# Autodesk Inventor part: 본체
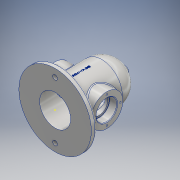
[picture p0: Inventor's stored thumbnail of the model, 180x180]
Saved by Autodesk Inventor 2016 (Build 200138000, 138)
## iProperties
Created: 2019-11
Part Number: 본체
Material: 알루미늄 6061
Document SubType Name: Modeling
Designer: 605-04
Density: 2.7 g/cm^3
Appearance: 알루미늄 - 평지
Mass: 1106.03 g
Surface Area: 883.156 cm^2
Volume: 409.64 cm^3
Author: 605-04
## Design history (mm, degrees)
sketch "스케치1"
  geometry: L1 (0, 0)-(-70, 0); L2 (-70, 0)-(-70, 10); L3 (-70, 10)-(-40, 10); L4 (-40, 10)-(-40, 135); L5 (-40, 135)-(0, 135); L6 (0, 135)-(0, 0); L7 (0, 90)-(-40, 90); L8 (0, 0)-(0, 161.363); L9 (-40, 90)-(-40, 10); L10 (40, 90)-(-40, 90); L11 (-30, 0)-(-30, 90); A1 r 40 centre (0, 90) between (-40, 90) and (40, 90)
  constraints: 22 end point, 7 perpendicular, 4 point on line, 2 collinear, 2 point on circle, 1 centre point, 1 coincident, 1 horizontal, 1 tangent, 1 vertical
  dimensions: "d0" = 70 distance of L1.start L1.end; "d1" = 10 distance between parallel lines of L1 L3; "d2" = 135 distance between parallel lines of L5 L1; "d4" = 90 distance of L1.start L7.start; "d6" = 10 distance between parallel lines of L4 L11; "d42" = 40 distance from line of L4 L1.start
revolve "회전1" sketch "스케치1" stored, may be unused: angle "d7" = 90 deg
sketch "스케치2"
  geometry: L1 (30, 90)-(-30, 90) reference; L2 (40, 10)-(40, 90) reference; L3 (-56.552, 90)-(56.552, 90); L4 (0, 0)-(0, 120); L5 (30, 0)-(-30, 0) reference; L6 (0, 120)-(0, 130); A1 r 30 centre (0, 90) between (0, 120) and (-30, 90); A2 r 40 centre (0, 90) between (0, 130) and (-40, 90); 4 further points
  constraints: 8 point on line, 7 end point, 4 point on circle, 2 centre point, 2 midpoint, 2 vertical, 1 coincident, 1 vertical alignment
  dimensions: "d38" = 60 diameter of A1; "d39" = 80 diameter of A2; "d40" = 90 distance between parallel lines of L5 L3 (derived)
node "작업 평면1"
sketch "스케치4"
  geometry: L1 (0, -70)-(0, 70) reference; C1 r 31 at (50, 0); C2 r 20 at (50, 0); 3 further points
  constraints: 2 centre point, 2 coincident, 1 horizontal alignment, 1 midpoint
  dimensions: "d10" = 50 distance from line of L1 point (50, 0); "d11" = 62 diameter of C1; "d12" = 40 diameter of C2
extrude "돌출1" join sketch "스케치4" stored distance "d13" = 0; taper "d14" = 0 deg
sketch "스케치5"
  geometry: L1 (70, -50)-(-70, -50) reference; 4 further points
  constraints: 2 vertical alignment, 1 midpoint
  dimensions: "d15" = 50 distance from line of L1 point (0, 0); "d16" = 26 distance of point (0, 26) point (0, 0)
hole "구멍1" sketch "스케치5" at (0, 26) diameter "d17" = 3.242; stored, may be unused: countersink angle "d21" = 90 deg, drill point angle "d23" = 118 deg; dims "d18" = 8, "d19" = 4, "d20" = 2, "d22" = 10
sketch "스케치6"
  geometry: 1 further point
fillet "모깎기1" dims "d32" = 3
node "작업 평면2"
node "작업 평면3"
sketch "스케치8"
  geometry: 1 further point
sketch "스케치9"
  geometry: C1 r 7.5 at (0, 0); 1 further point
  constraints: 1 centre point, 1 coincident
  dimensions: "d35" = 15 diameter of C1
revolve "회전3" stored, may be unused: angle "d41" = 90 deg
extrude "돌출3" join sketch "스케치9" stored distance "d43" = 10; taper "d44" = 0 deg
hole "구멍2" sketch "스케치8" diameter "d45" = 4.917; stored, may be unused: countersink angle "d49" = 90 deg, drill point angle "d51" = 118 deg; dims "d46" = 12, "d47" = 4, "d48" = 2, "d50" = 17.1
sketch "스케치11"
  geometry: L1 (-50, 30)-(-50, 70) reference; L2 (-50, 70)-(-35, 70); L3 (-35, 70)-(-35, 66.5); L4 (-30, 90)-(-30, 0) reference; L5 (-50, 50)-(50, 50); L6 (50, 81)-(50, 19) reference; L7 (-50, 70)-(-50, 50); L8 (-50, 50)-(-26.325, 50); L9 (-26.325, 50)-(-24.488, 50) reference; L10 (50, 30)-(50, 70) reference; L11 (35, 70)-(35, 66.5); L12 (35, 66.5)-(-35, 66.5); L13 (30, 90)-(30, 0) reference; L14 (30, 90)-(30, 0) reference; L15 (30, 90)-(30, 0) reference; L16 (35, 70)-(50, 70); L17 (50, 70)-(50, 50); 9 further points
  constraints: 18 end point, 8 point on line, 3 collinear, 3 midpoint, 3 perpendicular, 1 horizontal, 1 vertical
  dimensions: "d52" = 15 distance between parallel lines of L3 L1; "d65" = 15 distance from line of L11.start L10; "d66" = 33 diameter of L12 L5; "d67" = 40 diameter of L16 L5
revolve "회전4" stored, may be unused: angle "d54" = 90 deg
sketch "스케치12"
  geometry: 1 further point
fillet "모깎기2" dims "d55" = 3
sketch "스케치13"
  geometry: C1 r 4.5 at (0, 55); C2 r 4.5 at (0, -55); 1 further point
  constraints: 2 centre point, 2 vertical alignment
  dimensions: "d56" = 9 diameter of C1; "d57" = 55 distance of point (0, 0) C1.centre; "d58" = 9 diameter of C2; "d59" = 55 distance of C2.centre point (0, 0)
extrude "돌출4" cut sketch "스케치13" stored distance "d60" = 10; taper "d61" = 0 deg
node "작업 평면7"
sketch "스케치18"
  geometry: L1 (70, 0)-(-70, 0) reference; 2 further points
  constraints: 1 vertical alignment, 1 other
  dimensions: "d74" = 50 distance from line of L1 point (0, 50)
feature "엠보싱2" sketch "스케치18" dims "d75" = 0.5, "d76" = 0
chamfer "모따기2" distance "d77" = 1; stored, may be unused: second distance "d78" = 2, angle "d79" = 45 deg
fillet "모깎기3" dims "d80" = 0.3
node "솔리드1"
pattern_circular "원형 패턴1" dims angle "d25" = 360 deg
mirror "대칭1"
mirror "대칭2"
mirror "대칭3"
mirror "대칭4"
other parameters: "d33" = -135, "d34" = -135
